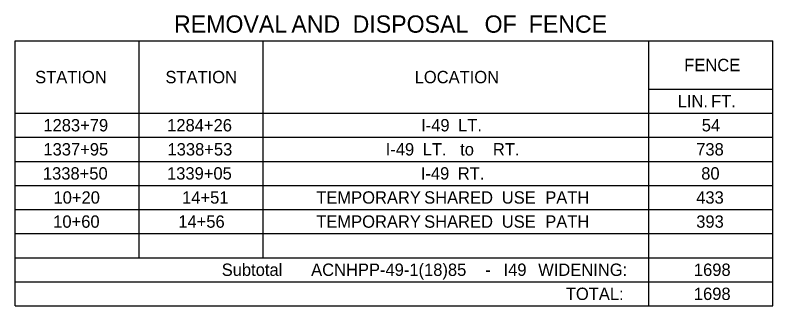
# Model space of a CAD drawing. Extents: x 1226657 to 1228145, y 151309 to 152305.
# Drawn here: x 1227557 to 1227863.7, y 152094.6 to 152212.3 of the extents above; entities that cross this region are included whole.
import ezdxf

# ---------------------------------------------------------------- set-up
doc = ezdxf.new("R2010")
doc.units = 0
doc.layers.add('R_Dimension', color=7, linetype='Continuous')

msp = doc.modelspace()

# ---------------------------------------------------------------- linework, layer by layer
at = {"layer": 'R_Dimension'}
for p, q in [((1227557.02, 152201.83), (1227863.66, 152201.83)), ((1227557.02, 152094.58), (1227557.02, 152201.83)), ((1227607.23, 152114.08), (1227607.23, 152201.83)), ((1227657.44, 152114.08), (1227657.44, 152201.83)), ((1227813.44, 152094.58), (1227813.44, 152201.83)), ((1227863.66, 152094.58), (1227863.66, 152201.83)), ((1227813.44, 152182.33), (1227863.66, 152182.33)), ((1227557.02, 152172.58), (1227863.66, 152172.58)), ((1227557.02, 152162.83), (1227863.66, 152162.83)), ((1227557.02, 152153.08), (1227863.66, 152153.08)), ((1227557.02, 152143.33), (1227863.66, 152143.33)), ((1227557.02, 152133.58), (1227863.66, 152133.58)), ((1227557.02, 152123.83), (1227863.66, 152123.83)), ((1227557.02, 152114.08), (1227863.66, 152114.08)), ((1227557.02, 152104.33), (1227863.66, 152104.33)), ((1227557.02, 152094.58), (1227863.66, 152094.58))]:
    msp.add_line(p, q, dxfattribs=at)

# ---------------------------------------------------------------- texts
for s, height, p in [('REMOVAL', 7, (1227621.32, 152205.15)), (' AND', 7, (1227666.19, 152205.15)), (' DISPOSAL', 7, (1227690.99, 152205.15)), (' OF', 7, (1227744.4, 152205.15)), (' FENCE', 7, (1227762.26, 152205.15)), ('FENCE', 5, (1227827.8, 152189.58)), ('STATION', 5, (1227565.12, 152184.7)), ('STATION', 5, (1227617.83, 152184.7)), ('LOCATION', 5, (1227718.69, 152184.7)), ('LIN.', 5, (1227825.14, 152174.95)), (' FT.', 5, (1227836.8, 152174.95)), ('1283+79', 5, (1227568.44, 152165.2)), ('1284+26', 5, (1227618.54, 152165.2)), ('I-49', 5, (1227721.31, 152165.2)), (' LT.', 5, (1227734.42, 152165.2)), ('54', 5, (1227834.89, 152165.2)), ('1337+95', 5, (1227568.46, 152155.45)), ('1338+53', 5, (1227618.68, 152155.45)), ('I-49', 5, (1227706.98, 152155.45)), (' LT.', 5, (1227720.09, 152155.45)), (' to', 5, (1227735.25, 152155.45)), (' RT.', 5, (1227748.51, 152155.45)), ('738', 5, (1227832.64, 152155.45)), ('1338+50', 5, (1227568.25, 152145.7)), ('1339+05', 5, (1227618.48, 152145.7)), ('I-49', 5, (1227721.19, 152145.7)), (' RT.', 5, (1227734.3, 152145.7)), ('80', 5, (1227834.67, 152145.7)), ('10+20', 5, (1227572.54, 152135.95)), ('14+51', 5, (1227624.58, 152135.95)), ('TEMPORARY', 5, (1227678.87, 152135.95)), (' SHARED', 5, (1227720.68, 152135.95)), (' USE', 5, (1227752.1, 152135.95)), (' PATH', 5, (1227769.7, 152135.95)), ('433', 5, (1227832.64, 152135.95)), ('10+60', 5, (1227572.42, 152126.2)), ('14+56', 5, (1227623.03, 152126.2)), ('TEMPORARY', 5, (1227678.87, 152126.2)), (' SHARED', 5, (1227720.68, 152126.2)), (' USE', 5, (1227752.1, 152126.2)), (' PATH', 5, (1227769.7, 152126.2)), ('393', 5, (1227832.64, 152126.2)), ('Subtotal', 5, (1227640.61, 152106.7)), (' ACNHPP-49-1(18)85', 5, (1227674.94, 152106.7)), (' I49', 5, (1227752.82, 152106.7)), (' WIDENING:', 5, (1227766.83, 152106.7)), ('1698', 5, (1227831.7, 152106.7)), (' -', 5, (1227745.38, 152106.7)), ('TOTAL:', 5, (1227779.87, 152096.95)), ('1698', 5, (1227831.7, 152096.95))]:
    msp.add_text(s, height=height, dxfattribs=at).set_placement(p)

doc.saveas('drawing.dxf')
